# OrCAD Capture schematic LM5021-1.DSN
size Custom; title: LM5021-1 SIMULATION EXAMPLE; rev: 1; note: Eric Lee
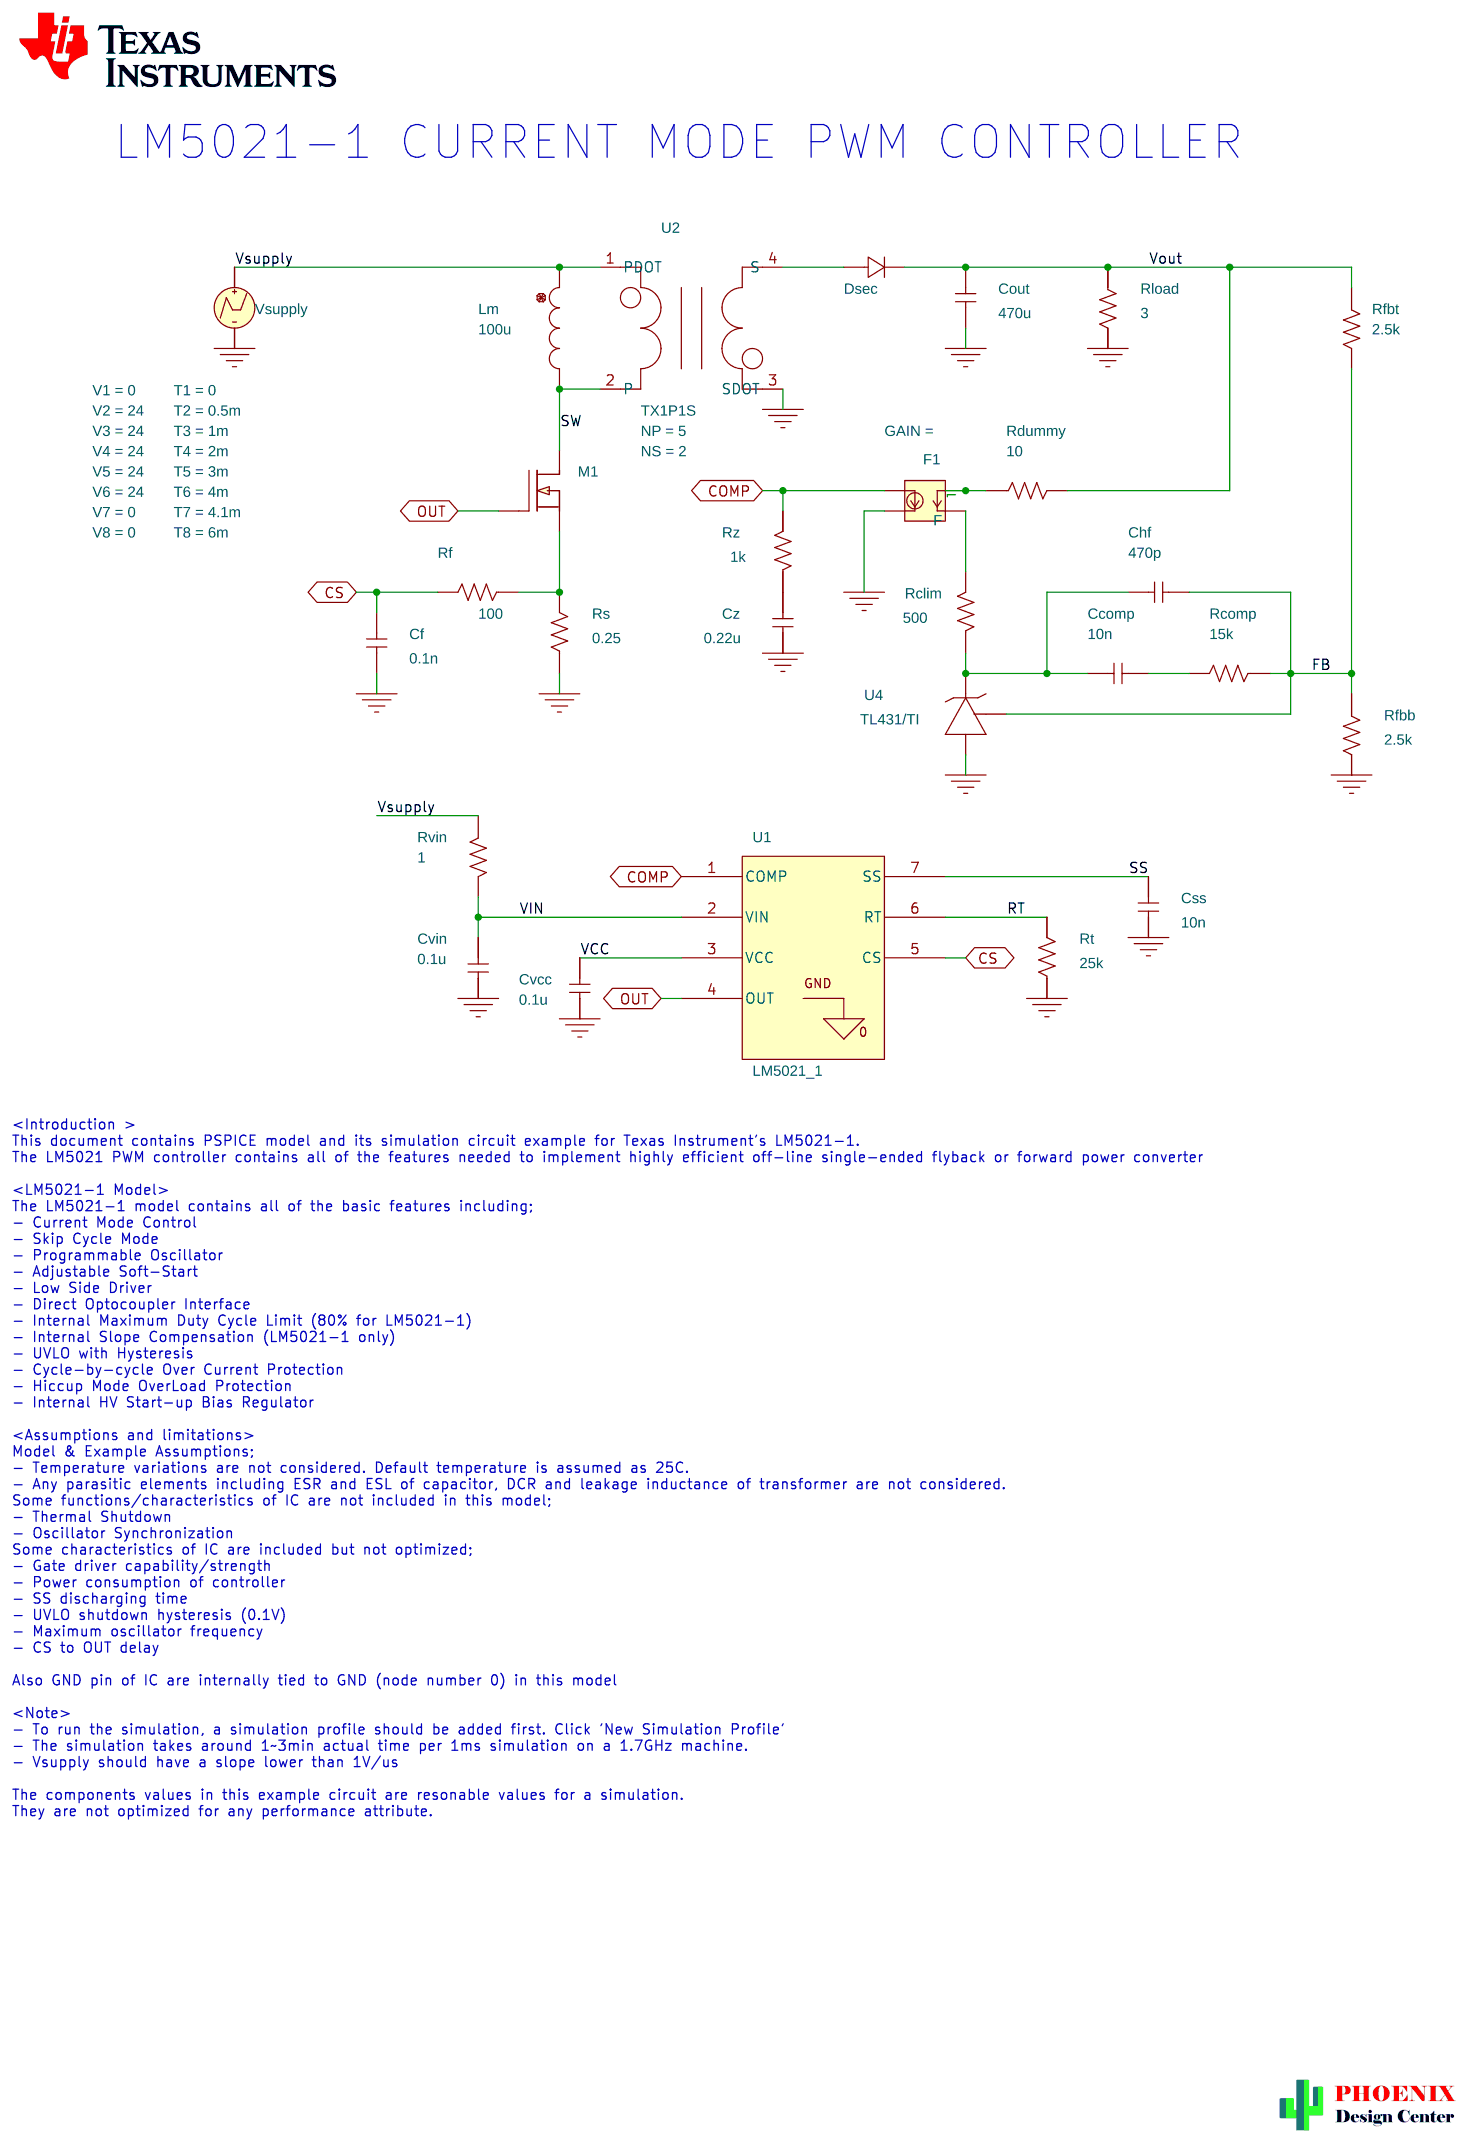
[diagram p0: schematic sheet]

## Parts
Ccomp  10n  [RAD/CK05]
Cf  0.1n  [RAD/CK05]
Chf  470p  [RAD/CK05]
Cout  470u  [RAD/CK05]
Css  10n  [RAD/CK05]
Cvcc  0.1u  [RAD/CK05]
Cvin  0.1u  [RAD/CK05]
Cz  0.22u  [RAD/CK05]
Dsec  Dbreak
F1  F
Lm  100u  [DISC/.350x.175/LS.200x.100/.034]
M1  NMOSnom
Rclim  500  [AX/RC05]
Rcomp  15k  [AX/RC05]
Rdummy  10  [AX/RC05]
Rf  100  [AX/RC05]
Rfbb  2.5k  [AX/RC05]
Rfbt  2.5k  [AX/RC05]
Rload  3  [AX/RC05]
Rs  0.25  [AX/RC05]
Rt  25k  [AX/RC05]
Rvin  1  [AX/RC05]
Rz  1k  [AX/RC05]
U1  LM5021_1
U2  TX1P1S
U4  TL431/TI
Vsupply  VPWL

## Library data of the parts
Ccomp Cf Chf Cout Css Cvcc Cvin Cz = C
Dsec = Dbreak
F1 = F
Lm = L
M1 = NMOSnom
Rclim Rcomp Rdummy Rf Rfbb Rfbt Rload Rs Rt Rvin Rz = R
U1 = LM5021_1
U2 = TX1P1S: NP: 5; NS: 2
U4 = TL431_TI
Vsupply = VPWL: T1: 0; T2: 0.5m; T3: 1m; T4: 2m; T5: 3m; T6: 4m; T7: 4.1m; T8: 6m; V1: 0; V2: 24; V3: 24; V4: 24; V5: 24; V6: 24; V7: 0; V8: 0

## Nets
VCC: Cvcc.2 U1.3(VCC)
VIN: Cvin.2 Rvin.2 U1.2(VIN)
0: Cf.1 Cout.1 Css.1 Cvcc.1 Cvin.1 Cz.2 F1.4 Rfbb.2 Rload.2 Rs.1 Rt.1 U2.3(SDOT) U4.2(AN) Vsupply.2(-)
COMP: F1.3 Rz.2 U1.1(COMP)
CS: Cf.2 Rf.2 U1.5(CS)
FB: Chf.1 Rcomp.1 Rfbb.1 Rfbt.2 U4.1(REF)
OUT: M1.3(g) U1.4(OUT)
RT: Rt.2 U1.6(RT)
SS: Css.2 U1.7(SS)
SW: Lm.2 M1.2(d) U2.2(P)
Vout: Cout.2 Dsec.1(2) Rdummy.2 Rfbt.1 Rload.1
Vsupply: Lm.1 Rvin.1 U2.1(PDOT) Vsupply.1(+)
N1654507: Dsec.0(1) U2.4(S)
N1654779: M1.1(s) Rf.1 Rs.2
N1654875: F1.2 Rclim.2
N1654909: Ccomp.2 Chf.2 Rclim.1 U4.3(CAT)
N1654921: F1.1 Rdummy.1
N1655019: Ccomp.1 Rcomp.2
N1657368: Cz.1 Rz.1

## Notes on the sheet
- LM5021-1 CURRENT MODE PWM CONTROLLER
- <Introduction >
  This document contains PSPICE model and its simulation circuit example for Texas Instrument's LM5021-1.
  The LM5021 PWM controller contains all of the features needed to implement highly efficient off-line single-ended flyback or forward power converter
  <LM5021-1 Model>
  The LM5021-1 model contains all of the basic features including;
  - Current Mode Control
  - Skip Cycle Mode
  - Programmable Oscillator
  - Adjustable Soft-Start
  - Low Side Driver
  - Direct Optocoupler Interface
  - Internal Maximum Duty Cycle Limit (80% for LM5021-1)
  - Internal Slope Compensation (LM5021-1 only)
  - UVLO with Hysteresis
  - Cycle-by-cycle Over Current Protection
  - Hiccup Mode OverLoad Protection
  - Internal HV Start-up Bias Regulator
  <Assumptions and limitations>
  Model & Example Assumptions;
  - Temperature variations are not considered. Default temperature is assumed as 25C.
  - Any parasitic elements including ESR and ESL of capacitor, DCR and leakage inductance of transformer are not considered.
  Some functions/characteristics of IC are not included in this model;
  - Thermal Shutdown
  - Oscillator Synchronization
  Some characteristics of IC are included but not optimized;
  - Gate driver capability/strength
  - Power consumption of controller
  - SS discharging time
  - UVLO shutdown hysteresis (0.1V)
  - Maximum oscillator frequency
  - CS to OUT delay
  Also GND pin of IC are internally tied to GND (node number 0) in this model
  <Note>
  - To run the simulation, a simulation profile should be added first. Click 'New Simulation Profile'
  - The simulation takes around 1~3min actual time per 1ms simulation on a 1.7GHz machine.
  - Vsupply should have a slope lower than 1V/us
  The components values in this example circuit are resonable values for a simulation.
  They are not optimized for any performance attribute.
